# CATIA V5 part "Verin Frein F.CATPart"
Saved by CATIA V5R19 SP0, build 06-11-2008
Part number: Verin Frein F
Bounding box of the stored display mesh (mm): x -90 to 90, y -1370 to -538, z -1569.911 to -1430.089
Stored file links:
  G:\EU_thinkMotion\CFAO_2010\MMS_groupe3\MMS_groupe3\rdalborgo\rdalborgo\Verin Frein F.CATPart
  G:\EU_thinkMotion\CFAO_2010\MMS_groupe3\MMS_groupe3\rdalborgo\rdalborgo\rdalborgo.CATProduct
  G:\EU_thinkMotion\CFAO_2010\MMS_groupe3\MMS_groupe3\rdalborgo\rdalborgo\Chape verin frein.CATPart
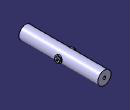
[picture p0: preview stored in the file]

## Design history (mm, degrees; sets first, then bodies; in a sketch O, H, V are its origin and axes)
Set1
  Plane1: linked copy from another document
  Line1: linked copy from another document
  Point1: linked copy from another document
  Point2: linked copy from another document
  Point3 "A verin frein": linked copy from another document
  Point4 "Cremaillere": linked copy from another document
Body1 (main body)
  Sketch1 on Plane1, origin (0, 0, 0), H (0, 1, 0), V (0, 0, 1)
    point P1 (-1370, -1499.997)
    line L1 (-1370, -1499.997) -> (-1369.9995, -1429.997)
    line L2 (-1369.9995, -1429.997) -> (-537.9995, -1430.0029)
    line L3 (-537.9995, -1430.0029) -> (-537.9999, -1485.0029)
    line L4 (-537.9999, -1485.0029) -> (-547.9999, -1485.0028)
    line L5 (-547.9999, -1485.0028) -> (-547.9996, -1450.0028)
    line L6 (-547.9996, -1450.0028) -> (-1359.9996, -1449.9971)
    line L7 (-1359.9996, -1449.9971) -> (-1360, -1499.9971)
    line L8 (-1360, -1499.9971) -> (-1370, -1499.997)
    reference projected line E1 (0, -1500.0067) -> (-1370, -1499.997) from Line1
    reference projected point E2 (-1370, -1499.997) from Point1
    reference projected line E3 (0, -1500.0067) -> (-1370, -1499.997) from Line1
    reference projected point E4 (-548, -1500.0028) from Point2
    distance L1 L7 = 10
    distance L5 L3 = 10
    distance L2 L6 = 20
    distance L8 L6 = 50
    distance L4 E3 = 15
    coincidence: L8 E1, P1 E2, L5 E4
    perpendicularity: L7 L6, L5 L6, L3 L4, L3 L2
  Shaft1: profile Sketch1, axis Line1, angle 360
  Sketch2 on Plane1, origin (0, 0, 0), H (0, 1, 0), V (0, 0, 1)
    circle A1 centre (-950, -1500) radius 35
    point P1 (-950, -1500)
    reference projected point E1 (-950, -1500) from Point3
    radius A1 = 35
    coincidence: P1 E1
  Pad1: profile Sketch2, direction (1, 0, 0), length 75, opposite side length -55
  Pad2: profile Sketch2, direction (-1, 0, 0), length 75, opposite side length -55
  Sketch3 on end face of Pad1, origin (75, 0, 0), H (0, 1, 0), V (0, 0, 1)
    circle A1 centre (-950, -1500) radius 25
    point P1 (-950, -1500)
    reference projected point E1 (-950, -1500) from Point3
    radius A1 = 25
    coincidence: P1 E1
  Pocket1: profile Sketch3, direction (-1, 0, 0), length 10
  Sketch4 on end face of Pocket1, origin (65, -950, -1500), H (0, 1, 0), V (0, 0, 1)
    point P1 (0, 0)
    reference projected point E1 (0, 0) from Point3
    coincidence: P1 E1
  Hole1: placed by Sketch4, at (65, -950, -1500) direction (-1, 0, 0), diameter 10, depth 13
  Sketch5 on end face of Pad2, origin (-75, 0, 0), H (0, -1, 0), V (0, 0, 1)
    circle A1 centre (950, -1500) radius 25
    point P1 (950, -1500)
    reference projected point E1 (950, -1500) from Point3
    radius A1 = 25
    coincidence: P1 E1
  Pocket2: profile Sketch5, direction (1, 0, 0), length 10
  Sketch6 on end face of Pocket2, origin (-65, -950, -1500), H (0, 1, 0), V (0, 0, -1)
    point P1 (0, 0)
    reference projected point E1 (0, 0) from Point3
    coincidence: P1 E1
  Hole2: placed by Sketch6, at (-65, -950, -1500) direction (1, 0, 0), diameter 10, depth 13
Body2 "Fixation 1"
  Sketch7 on end face of Pocket1, origin (65, 0, 0), H (0, 1, 0), V (0, 0, 1)
    circle A1 centre (-950, -1500) radius 5
    point P1 (-950, -1500)
    reference projected point E1 (-950, -1500) from Point3
    radius A1 = 5
    coincidence: P1 E1
  Pad3: profile Sketch7, direction (-1, 0, 0), length 10
  Chamfer1: length 1, angle 45, on edge [end face of Pad3 | face of Pad3 from Sketch7.A1]
  Sketch8 on start face of Pad3, origin (65, 0, 0), H (0, 1, 0), V (0, 0, 1)
    circle A1 centre (-950, -1500) radius 25
    point P1 (-950, -1500)
    reference projected point E1 (-950, -1500) from Point3
    radius A1 = 25
    coincidence: P1 E1
  Pad4: profile Sketch8, direction (1, 0, 0), length 25
  Sketch9 on end face of Pad4, origin (90, 0, 0), H (0, 1, 0), V (0, 0, 1)
    point P1 (-950, -1500)
    point P2 (-955.7735, -1510)
    point P3 (-944.2265, -1510)
    point P4 (-938.453, -1500)
    point P5 (-944.2265, -1490)
    point P6 (-955.7735, -1490)
    point P7 (-961.547, -1500)
    point P8 (-950, -1510)
    line L1 (-955.7735, -1510) -> (-944.2265, -1510)
    line L2 (-944.2265, -1510) -> (-938.453, -1500)
    line L3 (-938.453, -1500) -> (-944.2265, -1490)
    line L4 (-944.2265, -1490) -> (-955.7735, -1490)
    line L5 (-955.7735, -1490) -> (-961.547, -1500)
    line L6 (-961.547, -1500) -> (-955.7735, -1510)
    construction line L7 (-950, -1500) -> (-950, -1510)
    construction circle A1 centre (-950, -1500) radius 11.547
    construction arc A2 centre (-955.7735, -1490) radius 11.547 from (-944.2265, -1490) to (-961.547, -1500) cw
    construction arc A3 centre (-944.2265, -1510) radius 11.547 from (-938.453, -1500) to (-955.7735, -1510) ccw
    reference projected point E1 (-950, -1500) from Point3
    coincidence: A1 P2, A1 P3, A1 P4, A1 P5, A1 P6, A1 P7, A2 P1, A3 P1, P1 E1
    midpoint: P8 L1
    parallelism: L1 L4
  Pocket3: profile Sketch9, direction (-1, 0, 0), length 15
Body3 "Fixation 2"
  Sketch10 on end face of Pocket2, origin (-65, 0, 0), H (0, -1, 0), V (0, 0, 1)
    circle A1 centre (950, -1500) radius 5
    point P1 (950, -1500)
    reference projected point E1 (950, -1500) from Point3
    radius A1 = 5
    coincidence: P1 E1
  Pad5: profile Sketch10, direction (1, 0, 0), length 10
  Chamfer2: length 1, angle 45, on edge [end face of Pad5 | face of Pad5 from Sketch10.A1]
  Sketch11 on start face of Pad5, origin (-65, 0, 0), H (0, -1, 0), V (0, 0, 1)
    circle A1 centre (950, -1500) radius 25
    point P1 (950, -1500)
    reference projected point E1 (950, -1500) from Point3
    radius A1 = 25
    coincidence: P1 E1
  Pad6: profile Sketch11, direction (-1, 0, 0), length 25
  Sketch12 on end face of Pad6, origin (-90, 0, 0), H (0, -1, 0), V (0, 0, 1)
    point P1 (950, -1500)
    point P2 (944.2265, -1510)
    point P3 (955.7735, -1510)
    point P4 (961.547, -1500)
    point P5 (955.7735, -1490)
    point P6 (944.2265, -1490)
    point P7 (938.453, -1500)
    point P8 (950, -1510)
    line L1 (944.2265, -1510) -> (955.7735, -1510)
    line L2 (955.7735, -1510) -> (961.547, -1500)
    line L3 (961.547, -1500) -> (955.7735, -1490)
    line L4 (955.7735, -1490) -> (944.2265, -1490)
    line L5 (944.2265, -1490) -> (938.453, -1500)
    line L6 (938.453, -1500) -> (944.2265, -1510)
    construction line L7 (950, -1500) -> (950, -1510)
    construction circle A1 centre (950, -1500) radius 11.547
    construction arc A2 centre (944.2265, -1490) radius 11.547 from (955.7735, -1490) to (938.453, -1500) cw
    construction arc A3 centre (955.7735, -1510) radius 11.547 from (961.547, -1500) to (944.2265, -1510) ccw
    reference projected point E1 (950, -1500) from Point3
    coincidence: A1 P2, A1 P3, A1 P4, A1 P5, A1 P6, A1 P7, A2 P1, A3 P1, P1 E1
    midpoint: P8 L1
    parallelism: L1 L4
  Pocket4: profile Sketch12, direction (1, 0, 0), length 15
